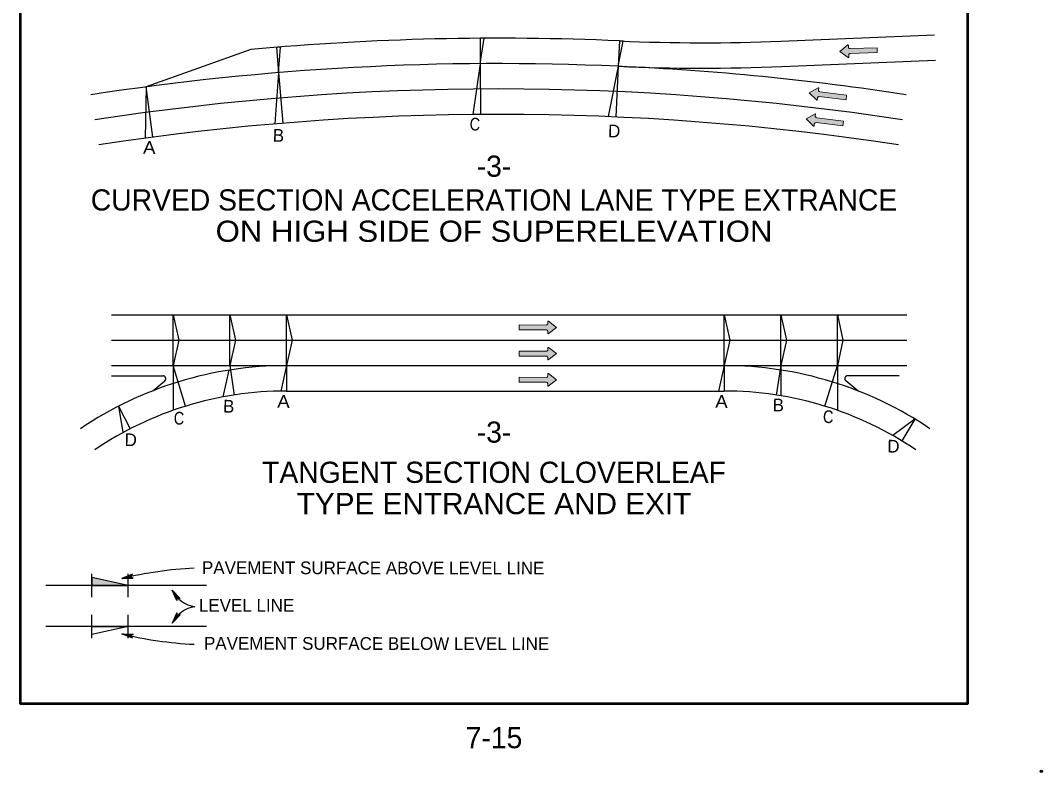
# Model space of a CAD drawing. Extents: x 0.641 to 1.316, y 2.867 to 3.751.
# Drawn here: x 0.686 to 1.316, y 2.867 to 3.331 of the extents above; entities that cross this region are included whole.
import ezdxf
from ezdxf.enums import TextEntityAlignment as Align

# ---------------------------------------------------------------- set-up
doc = ezdxf.new("R2010")
doc.units = 0
doc.header["$LTSCALE"] = 0.0031
doc.header["$PDMODE"] = 32
doc.header["$PDSIZE"] = 0.00155
doc.linetypes.add('DASH_DOUBLE_DOT', pattern=[9.2, 5, -1.2, 0.3, -1.2, 0.3, -1.2])
doc.linetypes.add('LONG_DASHED', pattern=[7.5, 6, -1.5])
for name, color, linetype, lineweight in [('1', 7, 'Continuous', 25), ('24', 7, 'Continuous', 25), ('60', 7, 'DASH_DOUBLE_DOT', 13)]:
    doc.layers.add(name, color=color, linetype=linetype, lineweight=lineweight)

msp = doc.modelspace()

# ---------------------------------------------------------------- hatches: boundary and pattern name
at = {"layer": '1'}
msp.add_hatch(color=256, dxfattribs=at).paths.add_polyline_path([(0.730367, 2.987425), (0.730367, 2.982508), (0.75285, 2.982508)])
at = {"layer": '60'}
for points in [[(1.197483, 3.310142), (1.197158, 3.310017), (1.196833, 3.309867), (1.19665, 3.309742), (1.196517, 3.309433), (1.196508, 3.3091), (1.19655, 3.307925), (1.196475, 3.307792), (1.196375, 3.307725), (1.196258, 3.307725), (1.196233, 3.307767), (1.191025, 3.311392), (1.195942, 3.315417), (1.19605, 3.31545), (1.196217, 3.315442), (1.19625, 3.3154), (1.196325, 3.315217), (1.196292, 3.31525), (1.196308, 3.314117), (1.196392, 3.313783), (1.196458, 3.313667), (1.196533, 3.313558), (1.196542, 3.31345), (1.19675, 3.313325), (1.196917, 3.313225), (1.197033, 3.313175), (1.197342, 3.313158), (1.213967, 3.31375), (1.214083, 3.310758)], [(1.178392, 3.28365), (1.178058, 3.283575), (1.177717, 3.283483), (1.177508, 3.283375), (1.177333, 3.283075), (1.177267, 3.282758), (1.177142, 3.2816), (1.177033, 3.281492), (1.176917, 3.28145), (1.176808, 3.281458), (1.176792, 3.281475), (1.172217, 3.2859), (1.177725, 3.2891), (1.17785, 3.289092), (1.177992, 3.289092), (1.178033, 3.289008), (1.178067, 3.28885), (1.178042, 3.288883), (1.177875, 3.287758), (1.1779, 3.287433), (1.17795, 3.287283), (1.177983, 3.287167), (1.178008, 3.287058), (1.178192, 3.286908), (1.178333, 3.286783), (1.178425, 3.2867), (1.17875, 3.28665), (1.19525, 3.284583), (1.1949, 3.281575)], [(1.17645, 3.267625), (1.176117, 3.26755), (1.175775, 3.267458), (1.175575, 3.267342), (1.175392, 3.267083), (1.175333, 3.266758), (1.175183, 3.265583), (1.175083, 3.265475), (1.174975, 3.265433), (1.174867, 3.265442), (1.17485, 3.265467), (1.170283, 3.269883), (1.175783, 3.273083), (1.1759, 3.2731), (1.176042, 3.273067), (1.176075, 3.272983), (1.176125, 3.272825), (1.1761, 3.272892), (1.175942, 3.27175), (1.175958, 3.271408), (1.176008, 3.271267), (1.17605, 3.27115), (1.176067, 3.271042), (1.176233, 3.270883), (1.176392, 3.270767), (1.176492, 3.2707), (1.176817, 3.270625), (1.193308, 3.268575), (1.192933, 3.265575)], [(1.010208, 3.142967), (1.010533, 3.143083), (1.010858, 3.143217), (1.01105, 3.14335), (1.011192, 3.14365), (1.011217, 3.143975), (1.011217, 3.14515), (1.0113, 3.145283), (1.011408, 3.145333), (1.011517, 3.145333), (1.011542, 3.145308), (1.0166, 3.141475), (1.011517, 3.137642), (1.011408, 3.137617), (1.011267, 3.137617), (1.011217, 3.137692), (1.011158, 3.137858), (1.011192, 3.1378), (1.011217, 3.13895), (1.011158, 3.139275), (1.011083, 3.139408), (1.011025, 3.139517), (1.011, 3.139625), (1.010808, 3.139758), (1.010642, 3.139867), (1.010533, 3.139925), (1.010208, 3.13995), (0.993592, 3.140008), (0.993592, 3.143025)], [(1.010208, 3.126833), (1.010533, 3.12695), (1.010858, 3.127083), (1.01105, 3.127217), (1.011192, 3.127517), (1.011217, 3.127842), (1.011217, 3.129017), (1.0113, 3.12915), (1.011408, 3.1292), (1.011517, 3.1292), (1.011542, 3.129175), (1.0166, 3.125342), (1.011517, 3.121508), (1.011408, 3.121483), (1.011267, 3.121483), (1.011217, 3.121558), (1.011158, 3.121725), (1.011192, 3.121667), (1.011217, 3.122817), (1.011158, 3.123142), (1.011083, 3.123275), (1.011025, 3.123383), (1.011, 3.123492), (1.010808, 3.123625), (1.010642, 3.123733), (1.010533, 3.123792), (1.010208, 3.123817), (0.993592, 3.123875), (0.993592, 3.126892)], [(1.010208, 3.1107), (1.010533, 3.110817), (1.010858, 3.11095), (1.01105, 3.111083), (1.011192, 3.111383), (1.011217, 3.111708), (1.011217, 3.112883), (1.0113, 3.113017), (1.011408, 3.113067), (1.011517, 3.113067), (1.011542, 3.113042), (1.0166, 3.109208), (1.011517, 3.105375), (1.011408, 3.10535), (1.011267, 3.10535), (1.011217, 3.105425), (1.011158, 3.105592), (1.011192, 3.105533), (1.011217, 3.106683), (1.011158, 3.107008), (1.011083, 3.107142), (1.011025, 3.10725), (1.011, 3.107358), (1.010808, 3.107492), (1.010642, 3.1076), (1.010533, 3.107658), (1.010208, 3.107683), (0.993592, 3.107742), (0.993592, 3.110758)]]:
    msp.add_hatch(color=256, dxfattribs=at).paths.add_polyline_path(points)

# ---------------------------------------------------------------- linework, layer by layer
at = {"layer": '1'}
for p, q in [((1.154783, 3.31775), (1.249308, 3.321683)), ((0.828267, 3.312558), (0.763908, 3.289617)), ((1.155433, 3.302142), (1.249958, 3.306075)), ((0.969617, 3.303908), (0.964983, 3.272617)), ((0.969617, 3.303908), (0.969833, 3.272658)), ((1.054583, 3.3023), (1.048333, 3.271292)), ((1.054583, 3.3023), (1.053183, 3.271075)), ((0.845375, 3.298367), (0.843108, 3.266817)), ((0.845375, 3.298367), (0.847942, 3.267225)), ((0.742425, 3.149208), (1.23235, 3.149208)), ((0.742425, 3.133583), (1.23235, 3.133583)), ((0.815342, 3.117958), (0.818133, 3.099875)), ((0.850225, 3.117958), (0.846767, 3.102308)), ((0.850225, 3.117958), (0.850225, 3.102333)), ((1.119775, 3.117958), (1.116317, 3.102308)), ((1.119775, 3.117958), (1.119775, 3.102333)), ((1.154658, 3.117958), (1.151867, 3.099875)), ((1.154658, 3.117958), (1.154658, 3.099425)), ((1.181842, 3.092983), (1.189542, 3.117958)), ((1.189542, 3.117958), (1.189542, 3.09045)), ((0.814725, 3.115158), (0.811075, 3.098667)), ((0.850225, 3.102333), (1.119775, 3.102333)), ((0.74685, 3.092967), (0.753983, 3.079067)), ((0.74685, 3.092967), (0.749567, 3.076733)), ((1.237258, 3.085075), (1.223608, 3.074975)), ((1.237258, 3.085075), (1.22915, 3.071725)), ((0.730367, 2.975283), (0.730367, 2.989742)), ((0.75285, 2.975283), (0.75285, 2.989742)), ((0.801017, 2.982508), (0.702, 2.982508)), ((0.730367, 2.950108), (0.730367, 2.964567)), ((0.75285, 2.950108), (0.75285, 2.964567)), ((0.801017, 2.957342), (0.702, 2.957342))]:
    msp.add_line(p, q, dxfattribs=at)
at = {"layer": '1', "linetype": 'LONG_DASHED'}
for p, q in [((0.742425, 3.111667), (0.774217, 3.111667)), ((1.227575, 3.111667), (1.195783, 3.111667)), ((0.767933, 3.102467), (0.775317, 3.108642)), ((1.202067, 3.102467), (1.194683, 3.108642))]:
    msp.add_line(p, q, dxfattribs=at)
at = {"layer": '1', "lineweight": 53}
msp.add_lwpolyline([(0.686417, 3.701267), (1.26975, 3.701267), (1.26975, 2.9096), (0.686417, 2.9096)], close=True, dxfattribs=at)
at = {"layer": '1'}
for points in [[(0.969508, 3.319525), (0.969617, 3.303908), (0.971942, 3.31955)], [(1.055275, 3.317908), (1.054583, 3.3023), (1.0577, 3.3178)], [(0.844092, 3.313942), (0.845375, 3.298367), (0.846508, 3.314142)], [(0.783908, 3.133583), (0.780458, 3.117958), (0.780458, 3.149208)], [(0.818792, 3.133583), (0.815342, 3.117958), (0.815342, 3.149208)], [(0.853675, 3.133583), (0.850225, 3.117958), (0.850225, 3.149208)], [(1.123225, 3.133583), (1.119775, 3.117958), (1.119775, 3.149208)], [(1.158108, 3.133583), (1.154658, 3.117958), (1.154658, 3.149208)], [(1.192992, 3.133583), (1.189542, 3.117958), (1.189542, 3.149208)], [(0.730367, 2.987425), (0.730367, 2.982508), (0.75285, 2.982508)], [(0.730367, 2.952425), (0.730367, 2.957342), (0.75285, 2.957342)]]:
    msp.add_lwpolyline(points, close=True, dxfattribs=at)
for points in [[(0.768017, 3.258633), (0.763908, 3.289617), (0.763208, 3.257992)], [(0.742425, 3.117958), (0.850225, 3.117958), (1.23235, 3.117958)], [(0.788158, 3.092983), (0.780458, 3.117958), (0.780458, 3.09045)]]:
    msp.add_lwpolyline(points, dxfattribs=at)
for centre, radius, start, end in [((0.980909, 1.653655), 1.665914, 87.44137, 95.25709), ((1.106821, 4.471356), 1.1546, 267.44137, 272.38083), ((0.980909, 1.653655), 1.650289, 87.44137, 98.74998), ((1.106821, 4.471356), 1.170225, 267.44137, 272.38083), ((0.980909, 1.653655), 1.650289, 81.25002, 87.44137), ((0.980909, 1.653655), 1.634664, 81.25002, 98.74998), ((0.980909, 1.653655), 1.619039, 81.25002, 98.74998), ((0.850225, 2.891639), 0.22632, 90, 124.06505), ((1.119775, 2.891639), 0.22632, 55.93495, 90), ((0.850225, 2.891639), 0.210695, 90, 124.06505), ((1.119775, 2.891639), 0.210695, 55.93495, 90), ((0.806131, 2.748283), 0.245323, 92.97337, 103.49169), ((0.796441, 2.987915), 0.018579, 206.51951, 262.05819), ((0.796441, 2.951113), 0.018579, 97.94181, 153.48049), ((0.806131, 3.191342), 0.245323, 256.50831, 267.02663)]:
    msp.add_arc(centre, radius, start, end, dxfattribs=at)
at = {"layer": '1', "linetype": 'LONG_DASHED'}
for centre, start, end in [((0.774219, 3.109953), 309.88634, 89.99996), ((1.19578, 3.109953), 90.00004, 230.11366)]:
    msp.add_arc(centre, 0.001711, start, end, dxfattribs=at)
at = {"layer": '1'}
msp.add_point((1.315133, 2.868158), dxfattribs=at)
at = {"layer": '24'}
for points in [[(0.7489, 2.986833), (0.755933, 2.987125), (0.754058, 2.987967), (0.755375, 2.989492), (0.7489, 2.986833), (0.74935, 2.986942), (0.755717, 2.987167), (0.753925, 2.98795), (0.755125, 2.989333), (0.749592, 2.987017), (0.749817, 2.987033), (0.755283, 2.98725), (0.753892, 2.98795), (0.754892, 2.989125), (0.749925, 2.987058), (0.750133, 2.98715), (0.754908, 2.987325), (0.753842, 2.987917), (0.754567, 2.988942), (0.7508, 2.987283), (0.751175, 2.987367), (0.754533, 2.987425), (0.753775, 2.987875), (0.7543, 2.988708), (0.75125, 2.98735), (0.751617, 2.9874), (0.754125, 2.987517), (0.75355, 2.987883), (0.753958, 2.988467), (0.751933, 2.9875), (0.752292, 2.98755), (0.7538, 2.987583), (0.753492, 2.987858), (0.7538, 2.988308), (0.752467, 2.987617), (0.75345, 2.987592), (0.753275, 2.987833), (0.753617, 2.988167), (0.752692, 2.987708), (0.753358, 2.987683), (0.753042, 2.987825), (0.753317, 2.988017), (0.753058, 2.987767), (0.753225, 2.987758)], [(0.779817, 2.979617), (0.784775, 2.974617), (0.782825, 2.975275), (0.78275, 2.973267), (0.779817, 2.979617), (0.780075, 2.979233), (0.784583, 2.974733), (0.782742, 2.975383), (0.782675, 2.97355), (0.7802, 2.979008), (0.78035, 2.97885), (0.784208, 2.974967), (0.782717, 2.9754), (0.78265, 2.973858), (0.780417, 2.978758), (0.780508, 2.978542), (0.783883, 2.975167), (0.7827, 2.975458), (0.782533, 2.974217), (0.7809, 2.977992), (0.781125, 2.977675), (0.783542, 2.97535), (0.782683, 2.975533), (0.7825, 2.974567), (0.781183, 2.977642), (0.781425, 2.97735), (0.783183, 2.975558), (0.782508, 2.975683), (0.782417, 2.974975), (0.781583, 2.977067), (0.781817, 2.976783), (0.7829, 2.975733), (0.782483, 2.975742), (0.782408, 2.9752), (0.7819, 2.976617), (0.782633, 2.975967), (0.782342, 2.975908), (0.782367, 2.975433), (0.782, 2.976392), (0.782508, 2.975958), (0.782175, 2.976075), (0.78225, 2.975742), (0.782233, 2.9761), (0.782358, 2.976)], [(0.779817, 2.959408), (0.784775, 2.964408), (0.782825, 2.96375), (0.78275, 2.965758), (0.779817, 2.959408), (0.780075, 2.959792), (0.784583, 2.964292), (0.782742, 2.963642), (0.782675, 2.965475), (0.7802, 2.960017), (0.78035, 2.960175), (0.784208, 2.964058), (0.782717, 2.963625), (0.78265, 2.965167), (0.780417, 2.960267), (0.780508, 2.960483), (0.783883, 2.963858), (0.7827, 2.963567), (0.782533, 2.964808), (0.7809, 2.961033), (0.781125, 2.96135), (0.783542, 2.963675), (0.782683, 2.963492), (0.7825, 2.964458), (0.781183, 2.961383), (0.781425, 2.961675), (0.783183, 2.963467), (0.782508, 2.963342), (0.782417, 2.96405), (0.781583, 2.961958), (0.781817, 2.962242), (0.7829, 2.963292), (0.782483, 2.963283), (0.782408, 2.963825), (0.7819, 2.962408), (0.782633, 2.963058), (0.782342, 2.963117), (0.782367, 2.963592), (0.782, 2.962633), (0.782508, 2.963067), (0.782175, 2.96295), (0.78225, 2.963283), (0.782233, 2.962925), (0.782358, 2.963025)], [(0.7489, 2.952792), (0.755933, 2.9525), (0.754058, 2.951658), (0.755375, 2.950133), (0.7489, 2.952792), (0.74935, 2.952683), (0.755717, 2.952458), (0.753925, 2.951675), (0.755125, 2.950292), (0.749592, 2.952608), (0.749817, 2.952592), (0.755283, 2.952375), (0.753892, 2.951675), (0.754892, 2.9505), (0.749925, 2.952567), (0.750133, 2.952475), (0.754908, 2.9523), (0.753842, 2.951708), (0.754567, 2.950683), (0.7508, 2.952342), (0.751175, 2.952258), (0.754533, 2.9522), (0.753775, 2.95175), (0.7543, 2.950917), (0.75125, 2.952275), (0.751617, 2.952225), (0.754125, 2.952108), (0.75355, 2.951742), (0.753958, 2.951158), (0.751933, 2.952125), (0.752292, 2.952075), (0.7538, 2.952042), (0.753492, 2.951767), (0.7538, 2.951317), (0.752467, 2.952008), (0.75345, 2.952033), (0.753275, 2.951792), (0.753617, 2.951458), (0.752692, 2.951917), (0.753358, 2.951942), (0.753042, 2.9518), (0.753317, 2.951608), (0.753058, 2.951858), (0.753225, 2.951867)]]:
    msp.add_lwpolyline(points, dxfattribs=at)
at = {"layer": '60'}
for points in [[(1.197483, 3.310142), (1.197158, 3.310017), (1.196833, 3.309867), (1.19665, 3.309742), (1.196517, 3.309433), (1.196508, 3.3091), (1.19655, 3.307925), (1.196475, 3.307792), (1.196375, 3.307725), (1.196258, 3.307725), (1.196233, 3.307767), (1.191025, 3.311392), (1.195942, 3.315417), (1.19605, 3.31545), (1.196217, 3.315442), (1.19625, 3.3154), (1.196325, 3.315217), (1.196292, 3.31525), (1.196308, 3.314117), (1.196392, 3.313783), (1.196458, 3.313667), (1.196533, 3.313558), (1.196542, 3.31345), (1.19675, 3.313325), (1.196917, 3.313225), (1.197033, 3.313175), (1.197342, 3.313158), (1.213967, 3.31375), (1.214083, 3.310758)], [(1.178392, 3.28365), (1.178058, 3.283575), (1.177717, 3.283483), (1.177508, 3.283375), (1.177333, 3.283075), (1.177267, 3.282758), (1.177142, 3.2816), (1.177033, 3.281492), (1.176917, 3.28145), (1.176808, 3.281458), (1.176792, 3.281475), (1.172217, 3.2859), (1.177725, 3.2891), (1.17785, 3.289092), (1.177992, 3.289092), (1.178033, 3.289008), (1.178067, 3.28885), (1.178042, 3.288883), (1.177875, 3.287758), (1.1779, 3.287433), (1.17795, 3.287283), (1.177983, 3.287167), (1.178008, 3.287058), (1.178192, 3.286908), (1.178333, 3.286783), (1.178425, 3.2867), (1.17875, 3.28665), (1.19525, 3.284583), (1.1949, 3.281575)], [(1.17645, 3.267625), (1.176117, 3.26755), (1.175775, 3.267458), (1.175575, 3.267342), (1.175392, 3.267083), (1.175333, 3.266758), (1.175183, 3.265583), (1.175083, 3.265475), (1.174975, 3.265433), (1.174867, 3.265442), (1.17485, 3.265467), (1.170283, 3.269883), (1.175783, 3.273083), (1.1759, 3.2731), (1.176042, 3.273067), (1.176075, 3.272983), (1.176125, 3.272825), (1.1761, 3.272892), (1.175942, 3.27175), (1.175958, 3.271408), (1.176008, 3.271267), (1.17605, 3.27115), (1.176067, 3.271042), (1.176233, 3.270883), (1.176392, 3.270767), (1.176492, 3.2707), (1.176817, 3.270625), (1.193308, 3.268575), (1.192933, 3.265575)], [(1.010208, 3.142967), (1.010533, 3.143083), (1.010858, 3.143217), (1.01105, 3.14335), (1.011192, 3.14365), (1.011217, 3.143975), (1.011217, 3.14515), (1.0113, 3.145283), (1.011408, 3.145333), (1.011517, 3.145333), (1.011542, 3.145308), (1.0166, 3.141475), (1.011517, 3.137642), (1.011408, 3.137617), (1.011267, 3.137617), (1.011217, 3.137692), (1.011158, 3.137858), (1.011192, 3.1378), (1.011217, 3.13895), (1.011158, 3.139275), (1.011083, 3.139408), (1.011025, 3.139517), (1.011, 3.139625), (1.010808, 3.139758), (1.010642, 3.139867), (1.010533, 3.139925), (1.010208, 3.13995), (0.993592, 3.140008), (0.993592, 3.143025)], [(1.010208, 3.126833), (1.010533, 3.12695), (1.010858, 3.127083), (1.01105, 3.127217), (1.011192, 3.127517), (1.011217, 3.127842), (1.011217, 3.129017), (1.0113, 3.12915), (1.011408, 3.1292), (1.011517, 3.1292), (1.011542, 3.129175), (1.0166, 3.125342), (1.011517, 3.121508), (1.011408, 3.121483), (1.011267, 3.121483), (1.011217, 3.121558), (1.011158, 3.121725), (1.011192, 3.121667), (1.011217, 3.122817), (1.011158, 3.123142), (1.011083, 3.123275), (1.011025, 3.123383), (1.011, 3.123492), (1.010808, 3.123625), (1.010642, 3.123733), (1.010533, 3.123792), (1.010208, 3.123817), (0.993592, 3.123875), (0.993592, 3.126892)], [(1.010208, 3.1107), (1.010533, 3.110817), (1.010858, 3.11095), (1.01105, 3.111083), (1.011192, 3.111383), (1.011217, 3.111708), (1.011217, 3.112883), (1.0113, 3.113017), (1.011408, 3.113067), (1.011517, 3.113067), (1.011542, 3.113042), (1.0166, 3.109208), (1.011517, 3.105375), (1.011408, 3.10535), (1.011267, 3.10535), (1.011217, 3.105425), (1.011158, 3.105592), (1.011192, 3.105533), (1.011217, 3.106683), (1.011158, 3.107008), (1.011083, 3.107142), (1.011025, 3.10725), (1.011, 3.107358), (1.010808, 3.107492), (1.010642, 3.1076), (1.010533, 3.107658), (1.010208, 3.107683), (0.993592, 3.107742), (0.993592, 3.110758)]]:
    msp.add_lwpolyline(points, close=True, dxfattribs=at)

# ---------------------------------------------------------------- texts
at = {"layer": '1'}
for s, width, p in [('C', 0.85, (0.966208, 3.26274)), ('A', 1.1, (0.765704, 3.248381)), ('A', 1.1, (0.848338, 3.092031)), ('A', 1.1, (1.118104, 3.091973)), ('C', 0.85, (0.783975, 3.081657)), ('C', 0.85, (1.183817, 3.08259))]:
    msp.add_text(s, height=0.007817, rotation=358.596, dxfattribs=dict(at, width=width)).set_placement(p, align=Align.CENTER)
for s, rotation, p in [('B', 358.596, (0.845229, 3.255834)), ('D', 358.596, (1.051996, 3.258516)), ('B', 358.596, (1.153071, 3.089809)), ('B', 358.596, (0.814604, 3.089059)), ('D', 358.596, (0.754238, 3.068382)), ('D', 358.596, (1.223979, 3.064424)), ('PAVEMENT SURFACE ABOVE LEVEL LINE', 359.92, (0.90364, 2.9895)), ('LEVEL LINE', 359.92, (0.825699, 2.966426)), ('PAVEMENT SURFACE BELOW LEVEL LINE', 359.92, (0.905774, 2.942938))]:
    msp.add_text(s, height=0.007817, rotation=rotation, dxfattribs=at).set_placement(p, align=Align.CENTER)
for s, p in [('-3-', (0.978087, 3.234258)), ('CURVED SECTION ACCELERATION LANE TYPE EXTRANCE', (0.978083, 3.213483)), ('-3-', (0.978087, 3.070533)), ('TANGENT SECTION CLOVERLEAF', (0.978087, 3.045758)), ('7-15', (0.978083, 2.882367))]:
    msp.add_text(s, height=0.01303, dxfattribs=at).set_placement(p, align=Align.CENTER)
for s, width, p in [('ON HIGH SIDE OF SUPERELEVATION', 1.1, (0.978083, 3.194208)), ('TYPE ENTRANCE AND EXIT', 1.05, (0.978083, 3.026483))]:
    msp.add_text(s, height=0.01303, dxfattribs=dict(at, width=width)).set_placement(p, align=Align.CENTER)

doc.saveas('drawing.dxf')
